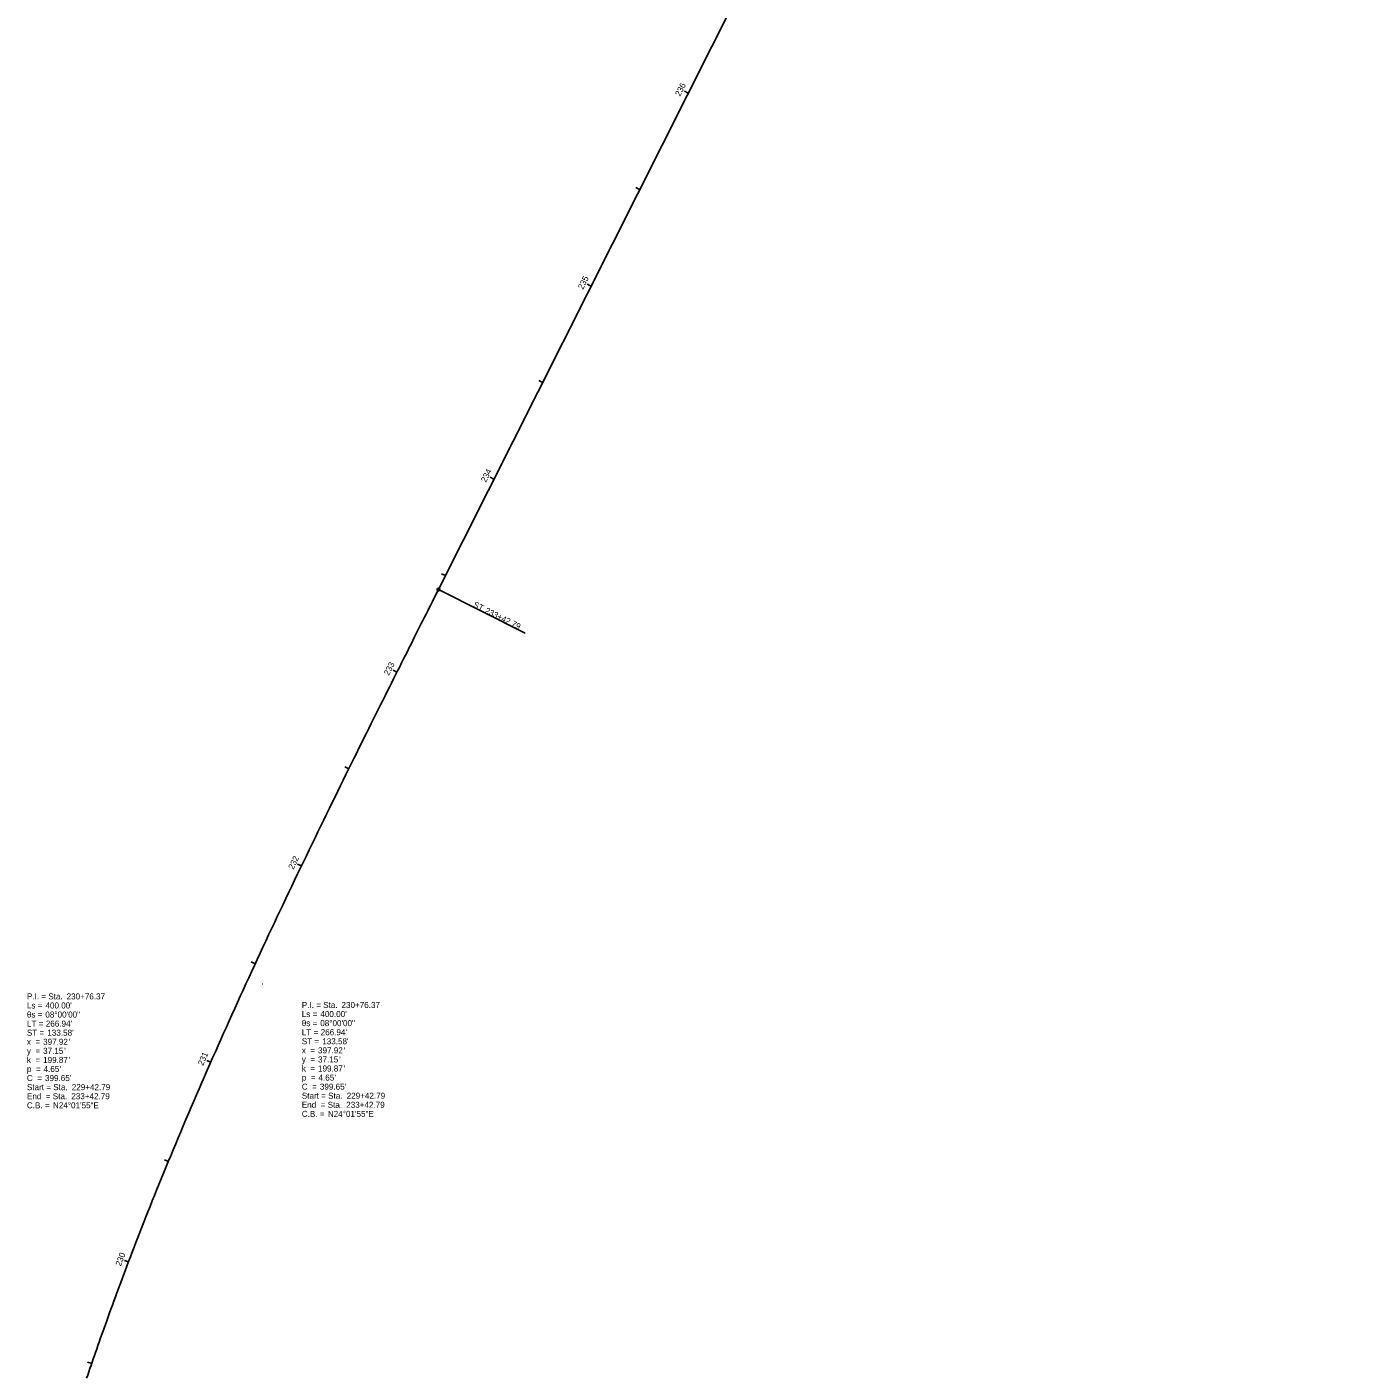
# Model space of a CAD drawing. Extents: x 1454426 to 1455277, y 587472 to 590476.
# Drawn here: x 1454479 to 1455102, y 589233 to 589855 of the extents above; entities that cross this region are included whole.
import ezdxf

# ---------------------------------------------------------------- set-up
doc = ezdxf.new("R2010")
doc.units = 0
for name, color, linetype in [('Default', 7, 'Continuous'), ('GT_Target_Soil_Boring', 7, 'Continuous'), ('RD_P_Wall', 7, 'Continuous'), ('RS_Raster2', 7, 'Continuous'), ('SC_Scratch1', 7, 'Continuous'), ('SC_Scratch2', 7, 'Continuous'), ('SC_Scratch3', 7, 'Continuous'), ('SC_Scratch4', 7, 'Continuous')]:
    doc.layers.add(name, color=color, linetype=linetype)

msp = doc.modelspace()

# ---------------------------------------------------------------- linework, layer by layer
at = {"layer": 'Default'}
for centre in [(1454784.79, 589824.14), (1454784.79, 589824.14), (1454784.79, 589824.14), (1454739.86, 589734.8), (1454739.86, 589734.8), (1454739.86, 589734.8), (1454694.93, 589645.46), (1454694.93, 589645.46), (1454694.93, 589645.46), (1454669.23, 589594.35), (1454669.23, 589594.35), (1454669.23, 589594.35), (1454650.02, 589556.12), (1454650.02, 589556.12), (1454650.02, 589556.12), (1454605.83, 589466.41), (1454605.83, 589466.41), (1454605.83, 589466.41), (1454587.85, 589411.85), (1454587.85, 589411.85), (1454587.85, 589411.85), (1454563.89, 589375.64), (1454563.89, 589375.64), (1454563.89, 589375.64), (1454525.84, 589283.17), (1454525.84, 589283.17), (1454525.84, 589283.17)]:
    msp.add_circle(centre, 0.0000833, dxfattribs=at)
at = {"layer": 'GT_Target_Soil_Boring'}
msp.add_line((1454669.23, 589594.35), (1455101.66, 590454.22), dxfattribs=at)
msp.add_open_spline([(1454506.47, 589229.34), (1454509.14, 589237.23), (1454514.62, 589252.97), (1454526.1, 589284.27), (1454541.33, 589323.06), (1454560.83, 589369.1), (1454581.33, 589414.71), (1454602.61, 589459.95), (1454624.49, 589504.92), (1454643.05, 589542.22), (1454657.99, 589572.02), (1454665.48, 589586.91), (1454669.23, 589594.35)], degree=3, dxfattribs=at)
at = {"layer": 'SC_Scratch1'}
for p, q in [((1454784.79, 589824.14), (1454783, 589825.04)), ((1454762.32, 589779.47), (1454760.54, 589780.37)), ((1454739.86, 589734.8), (1454738.07, 589735.7)), ((1454717.39, 589690.13), (1454715.61, 589691.03)), ((1454694.93, 589645.46), (1454693.14, 589646.36)), ((1454672.47, 589600.8), (1454670.68, 589601.69)), ((1454669.23, 589594.35), (1454709.43, 589574.13)), ((1454650.02, 589556.12), (1454648.23, 589557.01)), ((1454627.75, 589511.35), (1454625.95, 589512.24)), ((1454605.83, 589466.41), (1454604.03, 589467.28)), ((1454584.48, 589421.2), (1454582.66, 589422.04)), ((1454563.89, 589375.64), (1454562.06, 589376.44)), ((1454544.27, 589329.65), (1454542.42, 589330.41)), ((1454525.84, 589283.17), (1454523.97, 589283.88)), ((1454508.8, 589236.17), (1454506.91, 589236.82))]:
    msp.add_line(p, q, dxfattribs=at)
msp.add_circle((1454669.23, 589594.35), 0.6, dxfattribs=at)
at = {"layer": 'SC_Scratch2'}
for p, q in [((1454784.79, 589824.14), (1454783, 589825.04)), ((1454762.32, 589779.47), (1454760.54, 589780.37)), ((1454739.86, 589734.8), (1454738.07, 589735.7)), ((1454717.39, 589690.13), (1454715.61, 589691.03)), ((1454694.93, 589645.46), (1454693.14, 589646.36)), ((1454672.47, 589600.8), (1454670.68, 589601.69)), ((1454669.23, 589594.35), (1454709.43, 589574.13)), ((1454650.02, 589556.12), (1454648.23, 589557.01)), ((1454627.75, 589511.35), (1454625.95, 589512.24)), ((1454605.83, 589466.41), (1454604.03, 589467.28)), ((1454584.48, 589421.2), (1454582.66, 589422.04)), ((1454563.89, 589375.64), (1454562.06, 589376.44)), ((1454544.27, 589329.65), (1454542.42, 589330.41)), ((1454525.84, 589283.17), (1454523.97, 589283.88)), ((1454508.8, 589236.17), (1454506.91, 589236.82))]:
    msp.add_line(p, q, dxfattribs=at)
msp.add_circle((1454669.23, 589594.35), 0.6, dxfattribs=at)
at = {"layer": 'SC_Scratch3'}
for p, q in [((1454784.79, 589824.14), (1454783, 589825.04)), ((1454762.32, 589779.47), (1454760.54, 589780.37)), ((1454739.86, 589734.8), (1454738.07, 589735.7)), ((1454717.39, 589690.13), (1454715.61, 589691.03)), ((1454694.93, 589645.46), (1454693.14, 589646.36)), ((1454672.47, 589600.8), (1454670.68, 589601.69)), ((1454669.23, 589594.35), (1454709.43, 589574.13)), ((1454650.02, 589556.12), (1454648.23, 589557.01)), ((1454627.75, 589511.35), (1454625.95, 589512.24)), ((1454605.83, 589466.41), (1454604.03, 589467.28)), ((1454584.48, 589421.2), (1454582.66, 589422.04)), ((1454563.89, 589375.64), (1454562.06, 589376.44)), ((1454544.27, 589329.65), (1454542.42, 589330.41)), ((1454525.84, 589283.17), (1454523.97, 589283.88)), ((1454508.8, 589236.17), (1454506.91, 589236.82))]:
    msp.add_line(p, q, dxfattribs=at)
msp.add_circle((1454669.23, 589594.35), 0.6, dxfattribs=at)

# ---------------------------------------------------------------- texts
at = {"layer": 'RD_P_Wall'}
for s, p in [('P.I. = Sta. ', (1454606.02, 589400.69)), ('230+76.37', (1454624.39, 589400.69)), ('Ls = ', (1454606.02, 589396.49)), ("400.00'", (1454614.61, 589396.49)), ('θs = ', (1454606.02, 589392.29)), ('LT = ', (1454606.02, 589388.09)), ('08°00\'00"', (1454614.55, 589392.29)), ("266.94'", (1454614.75, 589388.09)), ('ST = ', (1454606.02, 589383.89)), ("133.58'", (1454615.47, 589383.89)), ('y  = ', (1454606.02, 589375.49)), ('x  = ', (1454606.02, 589379.69)), ('397.92', (1454613.52, 589379.69)), ('37.15', (1454613.52, 589375.49)), ("'", (1454623.3, 589375.49)), ("'", (1454625.48, 589379.69)), ('k  = ', (1454606.02, 589371.29)), ('199.87', (1454613.52, 589371.29)), ("'", (1454625.48, 589371.29)), ('C  = ', (1454606.02, 589362.89)), ('p  = ', (1454606.02, 589367.09)), ('4.65', (1454613.73, 589367.09)), ("399.65'", (1454614.39, 589362.89)), ("'", (1454621.35, 589367.09)), ('Start = Sta. ', (1454606.02, 589358.69)), ('229+42.79', (1454626.78, 589358.69)), ('C.B. = ', (1454606.02, 589350.29)), ('End  = Sta. ', (1454606.02, 589354.49)), ('N24°01\'55"E', (1454618.08, 589350.29)), ('233+42.79', (1454626.56, 589354.49))]:
    msp.add_text(s, height=2.8, dxfattribs=at).set_placement(p)
at = {"layer": 'RS_Raster2'}
for s, p in [('P.I. = Sta. ', (1454478.83, 589404.66)), ('Ls = ', (1454478.83, 589400.46)), ("400.00'", (1454487.41, 589400.46)), ('230+76.37', (1454497.2, 589404.66)), ('θs = ', (1454478.83, 589396.26)), ('08°00\'00"', (1454487.36, 589396.26)), ('ST = ', (1454478.83, 589387.86)), ('LT = ', (1454478.83, 589392.06)), ("266.94'", (1454487.56, 589392.06)), ("133.58'", (1454488.28, 589387.86)), ('x  = ', (1454478.83, 589383.66)), ('397.92', (1454486.33, 589383.66)), ("'", (1454498.29, 589383.66)), ('y  = ', (1454478.83, 589379.46)), ('k  = ', (1454478.83, 589375.26)), ('37.15', (1454486.33, 589379.46)), ('199.87', (1454486.33, 589375.26)), ("'", (1454496.11, 589379.46)), ("'", (1454498.29, 589375.26)), ('p  = ', (1454478.83, 589371.06)), ('4.65', (1454486.54, 589371.06)), ("'", (1454494.15, 589371.06)), ('Start = Sta. ', (1454478.83, 589362.66)), ('C  = ', (1454478.83, 589366.86)), ("399.65'", (1454487.2, 589366.86)), ('229+42.79', (1454499.59, 589362.66)), ('End  = Sta. ', (1454478.83, 589358.46)), ('233+42.79', (1454499.37, 589358.46)), ('C.B. = ', (1454478.83, 589354.26)), ('N24°01\'55"E', (1454490.89, 589354.26))]:
    msp.add_text(s, height=2.8, dxfattribs=at).set_placement(p)
at = {"layer": 'SC_Scratch1'}
for s, rotation, p in [('236', 63.30195, (1454781.04, 589822.35)), ('235', 63.30195, (1454736.1, 589733)), ('234', 63.30195, (1454691.2, 589643.72)), ('ST', 333.30195, (1454685.03, 589586.45)), ('233+42.79', 333.30195, (1454690.47, 589583.72)), ('233', 63.39349, (1454646.28, 589554.34)), ('232', 64.32136, (1454602.12, 589464.56)), ('231', 66.24924, (1454560.31, 589373.81)), ('230', 69.17712, (1454522.29, 589281.01))]:
    msp.add_text(s, height=2.8, rotation=rotation, dxfattribs=at).set_placement(p)
at = {"layer": 'SC_Scratch2'}
for s, rotation, p in [('236', 63.30195, (1454781.04, 589822.35)), ('235', 63.30195, (1454736.1, 589733)), ('234', 63.30195, (1454691.2, 589643.72)), ('ST', 333.30195, (1454685.03, 589586.45)), ('233+42.79', 333.30195, (1454690.47, 589583.72)), ('233', 63.39349, (1454646.28, 589554.34)), ('232', 64.32136, (1454602.12, 589464.56)), ('231', 66.24924, (1454560.31, 589373.81)), ('230', 69.17712, (1454522.29, 589281.01))]:
    msp.add_text(s, height=2.8, rotation=rotation, dxfattribs=at).set_placement(p)
at = {"layer": 'SC_Scratch3'}
for s, rotation, p in [('236', 63.30195, (1454781.04, 589822.35)), ('235', 63.30195, (1454736.1, 589733)), ('234', 63.30195, (1454691.2, 589643.72)), ('ST', 333.30195, (1454685.03, 589586.45)), ('233+42.79', 333.30195, (1454690.47, 589583.72)), ('233', 63.39349, (1454646.28, 589554.34)), ('232', 64.32136, (1454602.12, 589464.56)), ('231', 66.24924, (1454560.31, 589373.81)), ('230', 69.17712, (1454522.29, 589281.01))]:
    msp.add_text(s, height=2.8, rotation=rotation, dxfattribs=at).set_placement(p)
at = {"layer": 'SC_Scratch4'}
for s, p in [('P.I. = Sta. ', (1454606.02, 589400.69)), ('230+76.37', (1454624.39, 589400.69)), ('Ls = ', (1454606.02, 589396.49)), ("400.00'", (1454614.61, 589396.49)), ('θs = ', (1454606.02, 589392.29)), ('LT = ', (1454606.02, 589388.09)), ('08°00\'00"', (1454614.55, 589392.29)), ("266.94'", (1454614.75, 589388.09)), ('ST = ', (1454606.02, 589383.89)), ("133.58'", (1454615.47, 589383.89)), ('y  = ', (1454606.02, 589375.49)), ('x  = ', (1454606.02, 589379.69)), ('397.92', (1454613.52, 589379.69)), ('37.15', (1454613.52, 589375.49)), ("'", (1454623.3, 589375.49)), ("'", (1454625.48, 589379.69)), ('k  = ', (1454606.02, 589371.29)), ('199.87', (1454613.52, 589371.29)), ("'", (1454625.48, 589371.29)), ('C  = ', (1454606.02, 589362.89)), ('p  = ', (1454606.02, 589367.09)), ('4.65', (1454613.73, 589367.09)), ("399.65'", (1454614.39, 589362.89)), ("'", (1454621.35, 589367.09)), ('Start = Sta. ', (1454606.02, 589358.69)), ('229+42.79', (1454626.78, 589358.69)), ('C.B. = ', (1454606.02, 589350.29)), ('End  = Sta. ', (1454606.02, 589354.49)), ('N24°01\'55"E', (1454618.08, 589350.29)), ('233+42.79', (1454626.56, 589354.49))]:
    msp.add_text(s, height=2.8, dxfattribs=at).set_placement(p)

doc.saveas('drawing.dxf')
